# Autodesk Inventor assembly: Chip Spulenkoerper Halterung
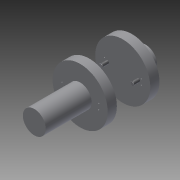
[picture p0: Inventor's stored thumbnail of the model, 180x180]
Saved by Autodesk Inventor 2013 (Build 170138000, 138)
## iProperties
Created: 2013-02
Part Number: Chip Spulenkoerper Halterung
Document SubType Name: Assembly
Designer: Hübner
Author: Hübner
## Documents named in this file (5)
- C:\Users\Hübner\Documents\SVN\2013\Inventor\SpulenWZ\Chip Spulenkoerper Halterung.iam
- C:\Users\Hübner\Documents\SVN\2013\Inventor\Kicker\Chip\Chip Spulenkoerper.ipt
- C:\Users\Hübner\Documents\SVN\2013\Inventor\SpulenWZ\Chip Spulenkoerper Halterung Spannung.ipt
- C:\Users\Hübner\Documents\SVN\2013\Inventor\SpulenWZ\Chip Spulenkoerper Halterung Spitze.ipt
- C:\Users\Hübner\Documents\SVN\2013\Inventor\SpulenWZ\DIN 438 - M4x14.ipt
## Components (7 placed, 4 different names)
1. Chip Spulenkörper:1 — Einfügen:5, Einfügen:6, Einfügen:7, Einfügen:8
2. Chip Spulenkoerper Halterung Spannung:1 — Einfügen:1, Einfügen:2, Einfügen:5, Einfügen:6
3. Chip Spulenkoerper Halterung Spitze:1 — Einfügen:3, Einfügen:4, Einfügen:7, Einfügen:8
4. DIN 438 M4x14:1 — Einfügen:1
5. DIN 438 M4x14:2 — Einfügen:2
6. DIN 438 M4x14:3 — Einfügen:3
7. DIN 438 M4x14:4 — Einfügen:4
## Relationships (8: Insert 8)
- Einfügen:1 [Insert]: Chip Spulenkoerper Halterung Spannung:1 ↔ DIN 438 M4x14:1
- Einfügen:2 [Insert]: Chip Spulenkoerper Halterung Spannung:1 ↔ DIN 438 M4x14:2
- Einfügen:3 [Insert]: Chip Spulenkoerper Halterung Spitze:1 ↔ DIN 438 M4x14:3
- Einfügen:4 [Insert]: Chip Spulenkoerper Halterung Spitze:1 ↔ DIN 438 M4x14:4
- Einfügen:5 [Insert]: Chip Spulenkörper:1 ↔ Chip Spulenkoerper Halterung Spannung:1
- Einfügen:6 [Insert]: Chip Spulenkörper:1 ↔ Chip Spulenkoerper Halterung Spannung:1
- Einfügen:7 [Insert]: Chip Spulenkörper:1 ↔ Chip Spulenkoerper Halterung Spitze:1
- Einfügen:8 [Insert]: Chip Spulenkörper:1 ↔ Chip Spulenkoerper Halterung Spitze:1
